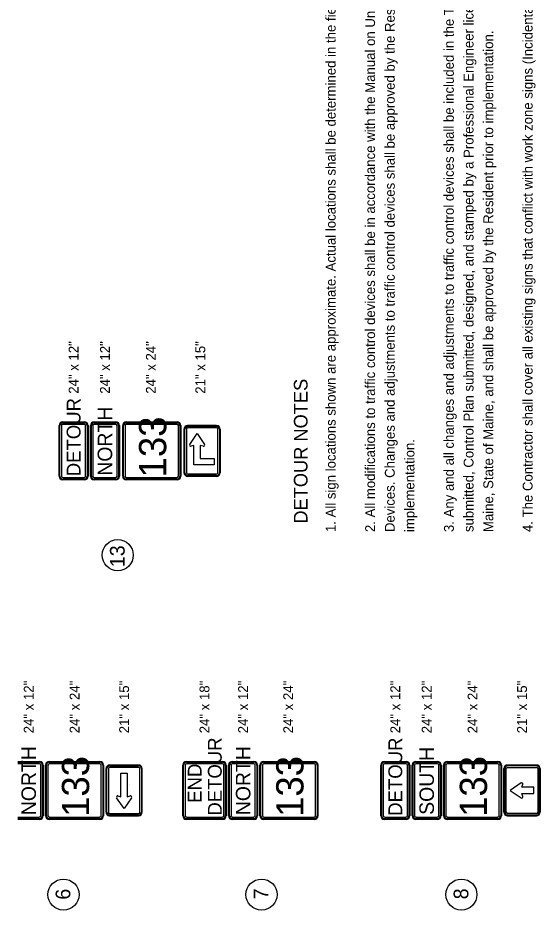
# Model space of a CAD drawing. Extents: x 1123038 to 1172987, y 554419 to 623636.
# Drawn here: x 1160788 to 1166729, y 559414 to 569560 of the extents above; entities that cross this region are included whole.
import ezdxf

# ---------------------------------------------------------------- set-up
doc = ezdxf.new("R2010")
doc.units = 0
for name, color, linetype in [('ANNOTATION', 7, 'Continuous'), ('D_Text_Standard', 7, 'Continuous'), ('Default', 7, 'Continuous'), ('SIGNS TRAFFIC', 7, 'Continuous')]:
    doc.layers.add(name, color=color, linetype=linetype)

msp = doc.modelspace()

# ---------------------------------------------------------------- linework, layer by layer
at = {"layer": 'D_Text_Standard'}
for centre in [(1161924, 563451), (1161307, 559591), (1163560, 559591), (1165833, 559591)]:
    msp.add_circle(centre, 177, dxfattribs=at)
at = {"layer": 'SIGNS TRAFFIC'}
for p, q in [((1163023, 564548), (1163023, 564476)), ((1161801, 560528), (1161801, 561023)), ((1166327, 561023), (1166327, 560528)), ((1161961, 560702), (1161961, 560971)), ((1161961, 560971), (1162033, 560971)), ((1162033, 560971), (1162033, 560702)), ((1166521, 560812), (1166532, 560845)), ((1166657, 560812), (1166521, 560812)), ((1166657, 560739), (1166657, 560812)), ((1161927, 560713), (1161961, 560702)), ((1162033, 560702), (1162066, 560713)), ((1166532, 560706), (1166521, 560739)), ((1166521, 560739), (1166657, 560739))]:
    msp.add_line(p, q, dxfattribs=at)
for points in [[(1161298, 564966), (1161546, 564966)], [(1161298, 564966), (1161546, 564966)], [(1161298, 564956), (1161546, 564956)], [(1161655, 564966), (1161902, 564966)], [(1161655, 564966), (1161902, 564966)], [(1161655, 564956), (1161902, 564956)], [(1162022, 564966), (1162600, 564966)], [(1162022, 564966), (1162600, 564966)], [(1162022, 564956), (1162600, 564956)], [(1161257, 564347), (1161257, 564925)], [(1161257, 564347), (1161257, 564925)], [(1161267, 564347), (1161267, 564925)], [(1161284, 564925), (1161284, 564347)], [(1161546, 564938), (1161298, 564938)], [(1161559, 564347), (1161559, 564925)], [(1161577, 564925), (1161577, 564347)], [(1161587, 564925), (1161587, 564347)], [(1161587, 564925), (1161587, 564347)], [(1161614, 564347), (1161614, 564925)], [(1161614, 564347), (1161614, 564925)], [(1161624, 564347), (1161624, 564925)], [(1161641, 564925), (1161641, 564347)], [(1161902, 564938), (1161655, 564938)], [(1161916, 564347), (1161916, 564925)], [(1161933, 564925), (1161933, 564347)], [(1161944, 564925), (1161944, 564347)], [(1161944, 564925), (1161944, 564347)], [(1161981, 564347), (1161981, 564925)], [(1161981, 564347), (1161981, 564925)], [(1161991, 564347), (1161991, 564925)], [(1162009, 564925), (1162009, 564347)], [(1162600, 564938), (1162022, 564938)], [(1162614, 564347), (1162614, 564925)], [(1162631, 564925), (1162631, 564347)], [(1162641, 564925), (1162641, 564347)], [(1162641, 564925), (1162641, 564347)], [(1162678, 564883), (1162678, 564388)], [(1162678, 564388), (1162678, 564883)], [(1162688, 564388), (1162688, 564883)], [(1162705, 564883), (1162705, 564388)], [(1163049, 564925), (1162719, 564925)], [(1162719, 564925), (1163049, 564925)], [(1162719, 564914), (1163049, 564914)], [(1163049, 564897), (1162719, 564897)], [(1163063, 564388), (1163063, 564883)], [(1163080, 564883), (1163080, 564388)], [(1163090, 564388), (1163090, 564883)], [(1163090, 564883), (1163090, 564388)], [(1162743, 564708), (1162827, 564832), (1162912, 564708)], [(1163023, 564476), (1162791, 564476), (1162791, 564699), (1162758, 564688)], [(1162897, 564688), (1162863, 564699), (1162863, 564548), (1163023, 564548)], [(1161298, 564333), (1161546, 564333)], [(1161655, 564333), (1161902, 564333)], [(1162022, 564333), (1162600, 564333)], [(1162719, 564375), (1163049, 564375)], [(1163049, 564358), (1162719, 564358)], [(1162719, 564347), (1163049, 564347)], [(1163049, 564347), (1162719, 564347)], [(1161546, 564316), (1161298, 564316)], [(1161546, 564306), (1161298, 564306)], [(1161546, 564306), (1161298, 564306)], [(1161902, 564316), (1161655, 564316)], [(1161902, 564306), (1161655, 564306)], [(1161902, 564306), (1161655, 564306)], [(1162600, 564316), (1162022, 564316)], [(1162600, 564306), (1162022, 564306)], [(1162600, 564306), (1162022, 564306)], [(1160788, 561106), (1161036, 561106)], [(1160788, 561106), (1161036, 561106)], [(1160788, 561095), (1161036, 561095)], [(1161145, 561106), (1161722, 561106)], [(1161145, 561106), (1161722, 561106)], [(1161145, 561095), (1161722, 561095)], [(1162705, 561106), (1163117, 561106)], [(1162705, 561106), (1163117, 561106)], [(1162705, 561095), (1163117, 561095)], [(1163226, 561106), (1163474, 561106)], [(1163226, 561106), (1163474, 561106)], [(1163226, 561095), (1163474, 561095)], [(1163583, 561106), (1164161, 561106)], [(1163583, 561106), (1164161, 561106)], [(1163583, 561095), (1164161, 561095)], [(1164957, 561106), (1165205, 561106)], [(1164957, 561106), (1165205, 561106)], [(1164957, 561095), (1165205, 561095)], [(1165314, 561106), (1165562, 561106)], [(1165314, 561106), (1165562, 561106)], [(1165314, 561095), (1165562, 561095)], [(1165671, 561106), (1166249, 561106)], [(1165671, 561106), (1166249, 561106)], [(1165671, 561095), (1166249, 561095)], [(1161036, 561078), (1160788, 561078)], [(1161049, 560487), (1161049, 561064)], [(1161066, 561064), (1161066, 560487)], [(1161077, 561064), (1161077, 560487)], [(1161077, 561064), (1161077, 560487)], [(1161104, 560487), (1161104, 561064)], [(1161104, 560487), (1161104, 561064)], [(1161114, 560487), (1161114, 561064)], [(1161131, 561064), (1161131, 560487)], [(1161722, 561078), (1161145, 561078)], [(1161736, 560487), (1161736, 561064)], [(1161753, 561064), (1161753, 560487)], [(1161764, 561064), (1161764, 560487)], [(1161764, 561064), (1161764, 560487)], [(1161790, 561023), (1161790, 560528)], [(1161818, 561023), (1161818, 560528)], [(1162162, 561064), (1161832, 561064)], [(1161832, 561054), (1162162, 561054)], [(1162162, 561037), (1161832, 561037)], [(1162175, 560528), (1162175, 561023)], [(1162193, 561023), (1162193, 560528)], [(1162203, 560528), (1162203, 561023)], [(1162663, 560487), (1162663, 561064)], [(1162663, 560487), (1162663, 561064)], [(1162674, 560487), (1162674, 561064)], [(1162691, 561064), (1162691, 560487)], [(1163117, 561078), (1162705, 561078)], [(1163131, 560487), (1163131, 561064)], [(1163148, 561064), (1163148, 560487)], [(1163158, 561064), (1163158, 560487)], [(1163158, 561064), (1163158, 560487)], [(1163185, 560487), (1163185, 561064)], [(1163185, 560487), (1163185, 561064)], [(1163195, 560487), (1163195, 561064)], [(1163213, 561064), (1163213, 560487)], [(1163474, 561078), (1163226, 561078)], [(1163488, 560487), (1163488, 561064)], [(1163505, 561064), (1163505, 560487)], [(1163515, 561064), (1163515, 560487)], [(1163515, 561064), (1163515, 560487)], [(1163542, 560487), (1163542, 561064)], [(1163542, 560487), (1163542, 561064)], [(1163552, 560487), (1163552, 561064)], [(1163569, 561064), (1163569, 560487)], [(1164161, 561078), (1163583, 561078)], [(1164174, 560487), (1164174, 561064)], [(1164192, 561064), (1164192, 560487)], [(1164202, 561064), (1164202, 560487)], [(1164202, 561064), (1164202, 560487)], [(1164916, 560487), (1164916, 561064)], [(1164916, 560487), (1164916, 561064)], [(1164927, 560487), (1164927, 561064)], [(1164944, 561064), (1164944, 560487)], [(1165205, 561078), (1164957, 561078)], [(1165219, 560487), (1165219, 561064)], [(1165236, 561064), (1165236, 560487)], [(1165246, 561064), (1165246, 560487)], [(1165246, 561064), (1165246, 560487)], [(1165273, 560487), (1165273, 561064)], [(1165273, 560487), (1165273, 561064)], [(1165283, 560487), (1165283, 561064)], [(1165301, 561064), (1165301, 560487)], [(1165562, 561078), (1165314, 561078)], [(1165576, 560487), (1165576, 561064)], [(1165593, 561064), (1165593, 560487)], [(1165603, 561064), (1165603, 560487)], [(1165603, 561064), (1165603, 560487)], [(1165630, 560487), (1165630, 561064)], [(1165630, 560487), (1165630, 561064)], [(1165640, 560487), (1165640, 561064)], [(1165657, 561064), (1165657, 560487)], [(1166249, 561078), (1165671, 561078)], [(1166262, 560487), (1166262, 561064)], [(1166280, 561064), (1166280, 560487)], [(1166290, 561064), (1166290, 560487)], [(1166290, 561064), (1166290, 560487)], [(1166317, 560528), (1166317, 561023)], [(1166317, 561023), (1166317, 560528)], [(1166344, 560528), (1166344, 561023)], [(1166358, 561064), (1166688, 561064)], [(1166688, 561064), (1166358, 561064)], [(1166688, 561054), (1166358, 561054)], [(1166358, 561037), (1166688, 561037)], [(1166702, 561023), (1166702, 560528)], [(1166719, 560528), (1166719, 561023)], [(1166729, 561023), (1166729, 560528)], [(1166729, 560528), (1166729, 561023)], [(1162054, 560846), (1162054, 560845)], [(1166513, 560860), (1166389, 560776), (1166513, 560691)], [(1162081, 560693), (1161997, 560569), (1161912, 560693)], [(1161832, 560514), (1162162, 560514)], [(1162162, 560497), (1161832, 560497)], [(1161832, 560487), (1162162, 560487)], [(1166688, 560514), (1166358, 560514)], [(1166358, 560497), (1166688, 560497)], [(1166688, 560487), (1166358, 560487)], [(1166358, 560487), (1166688, 560487)], [(1160788, 560473), (1161036, 560473)], [(1161036, 560456), (1160788, 560456)], [(1161036, 560446), (1160788, 560446)], [(1161036, 560446), (1160788, 560446)], [(1161145, 560473), (1161722, 560473)], [(1161722, 560456), (1161145, 560456)], [(1161722, 560446), (1161145, 560446)], [(1161722, 560446), (1161145, 560446)], [(1162705, 560473), (1163117, 560473)], [(1163117, 560456), (1162705, 560456)], [(1163117, 560446), (1162705, 560446)], [(1163117, 560446), (1162705, 560446)], [(1163226, 560473), (1163474, 560473)], [(1163474, 560456), (1163226, 560456)], [(1163474, 560446), (1163226, 560446)], [(1163474, 560446), (1163226, 560446)], [(1163583, 560473), (1164161, 560473)], [(1164161, 560456), (1163583, 560456)], [(1164161, 560446), (1163583, 560446)], [(1164161, 560446), (1163583, 560446)], [(1164957, 560473), (1165205, 560473)], [(1165205, 560456), (1164957, 560456)], [(1165205, 560446), (1164957, 560446)], [(1165205, 560446), (1164957, 560446)], [(1165314, 560473), (1165562, 560473)], [(1165562, 560456), (1165314, 560456)], [(1165562, 560446), (1165314, 560446)], [(1165562, 560446), (1165314, 560446)], [(1165671, 560473), (1166249, 560473)], [(1166249, 560456), (1165671, 560456)], [(1166249, 560446), (1165671, 560446)], [(1166249, 560446), (1165671, 560446)]]:
    msp.add_lwpolyline(points, dxfattribs=at)
for centre, radius, start, end in [((1161298, 564925), 41.2, 90, 180), ((1161298, 564925), 41.2, 90, 180), ((1161298, 564925), 30.9, 90, 180), ((1161546, 564925), 41.2, 360, 90), ((1161546, 564925), 41.2, 360, 90), ((1161546, 564925), 30.9, 360, 90), ((1161655, 564925), 41.2, 90, 180), ((1161655, 564925), 41.2, 90, 180), ((1161655, 564925), 30.9, 90, 180), ((1161902, 564925), 41.2, 360, 90), ((1161902, 564925), 41.2, 360, 90), ((1161902, 564925), 30.9, 360, 90), ((1162022, 564925), 41.2, 90, 180), ((1162022, 564925), 41.2, 90, 180), ((1162022, 564925), 30.9, 90, 180), ((1162600, 564925), 41.2, 360, 90), ((1162600, 564925), 41.2, 360, 90), ((1162600, 564925), 30.9, 360, 90), ((1161298, 564925), 13.7, 90, 180), ((1161546, 564925), 13.7, 360, 90), ((1161655, 564925), 13.7, 90, 180), ((1161902, 564925), 13.7, 360, 90), ((1162022, 564925), 13.7, 90, 180), ((1162600, 564925), 13.7, 360, 90), ((1162719, 564883), 41.2, 90, 180), ((1162719, 564883), 41.2, 90, 180), ((1162719, 564883), 30.9, 90, 180), ((1162719, 564883), 13.7, 90, 180), ((1163049, 564883), 41.2, 360, 90), ((1163049, 564883), 41.2, 360, 90), ((1163049, 564883), 30.9, 360, 90), ((1163049, 564883), 13.7, 360, 90), ((1162754, 564701), 12.9, 145.6763, 287.8128), ((1162901, 564701), 12.9, 252.1872, 34.3237), ((1161298, 564347), 41.2, 180, 270), ((1161298, 564347), 41.2, 180, 270), ((1161298, 564347), 30.9, 180, 270), ((1161298, 564347), 13.7, 180, 270), ((1161546, 564347), 41.2, 270, 360), ((1161546, 564347), 41.2, 270, 360), ((1161546, 564347), 30.9, 270, 360), ((1161546, 564347), 13.7, 270, 360), ((1161655, 564347), 41.2, 180, 270), ((1161655, 564347), 41.2, 180, 270), ((1161655, 564347), 30.9, 180, 270), ((1161655, 564347), 13.7, 180, 270), ((1161902, 564347), 41.2, 270, 360), ((1161902, 564347), 41.2, 270, 360), ((1161902, 564347), 30.9, 270, 360), ((1161902, 564347), 13.7, 270, 360), ((1162022, 564347), 41.2, 180, 270), ((1162022, 564347), 41.2, 180, 270), ((1162022, 564347), 30.9, 180, 270), ((1162022, 564347), 13.7, 180, 270), ((1162600, 564347), 41.2, 270, 360), ((1162600, 564347), 41.2, 270, 360), ((1162600, 564347), 30.9, 270, 360), ((1162600, 564347), 13.7, 270, 360), ((1162719, 564388), 41.2, 180, 270), ((1162719, 564388), 41.2, 180, 270), ((1162719, 564388), 30.9, 180, 270), ((1162719, 564388), 13.7, 180, 270), ((1163049, 564388), 41.2, 270, 0), ((1163049, 564388), 41.2, 270, 0), ((1163049, 564388), 30.9, 270, 0), ((1163049, 564388), 13.7, 270, 0), ((1161036, 561064), 41.2, 360, 90), ((1161036, 561064), 41.2, 360, 90), ((1161036, 561064), 30.9, 360, 90), ((1161145, 561064), 41.2, 90, 180), ((1161145, 561064), 41.2, 90, 180), ((1161145, 561064), 30.9, 90, 180), ((1161722, 561064), 41.2, 360, 90), ((1161722, 561064), 41.2, 360, 90), ((1161722, 561064), 30.9, 360, 90), ((1162705, 561064), 41.2, 90, 180), ((1162705, 561064), 41.2, 90, 180), ((1162705, 561064), 30.9, 90, 180), ((1163117, 561064), 41.2, 360, 90), ((1163117, 561064), 41.2, 360, 90), ((1163117, 561064), 30.9, 360, 90), ((1163226, 561064), 41.2, 90, 180), ((1163226, 561064), 41.2, 90, 180), ((1163226, 561064), 30.9, 90, 180), ((1163474, 561064), 41.2, 360, 90), ((1163474, 561064), 41.2, 360, 90), ((1163474, 561064), 30.9, 360, 90), ((1163583, 561064), 41.2, 90, 180), ((1163583, 561064), 41.2, 90, 180), ((1163583, 561064), 30.9, 90, 180), ((1164161, 561064), 41.2, 360, 90), ((1164161, 561064), 41.2, 360, 90), ((1164161, 561064), 30.9, 360, 90), ((1164957, 561064), 41.2, 90, 180), ((1164957, 561064), 41.2, 90, 180), ((1164957, 561064), 30.9, 90, 180), ((1165205, 561064), 41.2, 360, 90), ((1165205, 561064), 41.2, 360, 90), ((1165205, 561064), 30.9, 360, 90), ((1165314, 561064), 41.2, 90, 180), ((1165314, 561064), 41.2, 90, 180), ((1165314, 561064), 30.9, 90, 180), ((1165562, 561064), 41.2, 360, 90), ((1165562, 561064), 41.2, 360, 90), ((1165562, 561064), 30.9, 360, 90), ((1165671, 561064), 41.2, 90, 180), ((1165671, 561064), 41.2, 90, 180), ((1165671, 561064), 30.9, 90, 180), ((1166249, 561064), 41.2, 360, 90), ((1166249, 561064), 41.2, 360, 90), ((1166249, 561064), 30.9, 360, 90), ((1161036, 561064), 13.7, 360, 90), ((1161145, 561064), 13.7, 90, 180), ((1161722, 561064), 13.7, 360, 90), ((1161832, 561023), 41.2, 90, 180), ((1161832, 561023), 30.9, 90, 180), ((1161832, 561023), 13.7, 90, 180), ((1162162, 561023), 41.2, 360, 90), ((1162162, 561023), 30.9, 360, 90), ((1162162, 561023), 13.7, 360, 90), ((1162705, 561064), 13.7, 90, 180), ((1163117, 561064), 13.7, 360, 90), ((1163226, 561064), 13.7, 90, 180), ((1163474, 561064), 13.7, 360, 90), ((1163583, 561064), 13.7, 90, 180), ((1164161, 561064), 13.7, 360, 90), ((1164957, 561064), 13.7, 90, 180), ((1165205, 561064), 13.7, 360, 90), ((1165314, 561064), 13.7, 90, 180), ((1165562, 561064), 13.7, 360, 90), ((1165671, 561064), 13.7, 90, 180), ((1166249, 561064), 13.7, 360, 90), ((1166358, 561023), 41.2, 90, 180), ((1166358, 561023), 41.2, 90, 180), ((1166358, 561023), 30.9, 90, 180), ((1166358, 561023), 13.7, 90, 180), ((1166688, 561023), 41.2, 360, 90), ((1166688, 561023), 41.2, 360, 90), ((1166688, 561023), 30.9, 360, 90), ((1166688, 561023), 13.7, 360, 90), ((1166520, 560849), 12.9, 342.1872, 124.3237), ((1161923, 560700), 12.9, 72.1872, 214.3237), ((1162070, 560700), 12.9, 325.6763, 107.8128), ((1166520, 560702), 12.9, 235.6763, 17.8128), ((1161036, 560487), 41.2, 270, 360), ((1161036, 560487), 41.2, 270, 360), ((1161036, 560487), 30.9, 270, 360), ((1161036, 560487), 13.7, 270, 360), ((1161145, 560487), 41.2, 180, 270), ((1161145, 560487), 41.2, 180, 270), ((1161145, 560487), 30.9, 180, 270), ((1161145, 560487), 13.7, 180, 270), ((1161722, 560487), 41.2, 270, 360), ((1161722, 560487), 41.2, 270, 360), ((1161722, 560487), 30.9, 270, 360), ((1161722, 560487), 13.7, 270, 360), ((1161832, 560528), 41.2, 180, 270), ((1161832, 560528), 30.9, 180, 270), ((1161832, 560528), 13.7, 180, 270), ((1162162, 560528), 41.2, 270, 0), ((1162162, 560528), 30.9, 270, 0), ((1162162, 560528), 13.7, 270, 0), ((1162705, 560487), 41.2, 180, 270), ((1162705, 560487), 41.2, 180, 270), ((1162705, 560487), 30.9, 180, 270), ((1162705, 560487), 13.7, 180, 270), ((1163117, 560487), 41.2, 270, 360), ((1163117, 560487), 41.2, 270, 360), ((1163117, 560487), 30.9, 270, 360), ((1163117, 560487), 13.7, 270, 360), ((1163226, 560487), 41.2, 180, 270), ((1163226, 560487), 41.2, 180, 270), ((1163226, 560487), 30.9, 180, 270), ((1163226, 560487), 13.7, 180, 270), ((1163474, 560487), 41.2, 270, 360), ((1163474, 560487), 41.2, 270, 360), ((1163474, 560487), 30.9, 270, 360), ((1163474, 560487), 13.7, 270, 360), ((1163583, 560487), 41.2, 180, 270), ((1163583, 560487), 41.2, 180, 270), ((1163583, 560487), 30.9, 180, 270), ((1163583, 560487), 13.7, 180, 270), ((1164161, 560487), 41.2, 270, 360), ((1164161, 560487), 41.2, 270, 360), ((1164161, 560487), 30.9, 270, 360), ((1164161, 560487), 13.7, 270, 360), ((1164957, 560487), 41.2, 180, 270), ((1164957, 560487), 41.2, 180, 270), ((1164957, 560487), 30.9, 180, 270), ((1164957, 560487), 13.7, 180, 270), ((1165205, 560487), 41.2, 270, 360), ((1165205, 560487), 41.2, 270, 360), ((1165205, 560487), 30.9, 270, 360), ((1165205, 560487), 13.7, 270, 360), ((1165314, 560487), 41.2, 180, 270), ((1165314, 560487), 41.2, 180, 270), ((1165314, 560487), 30.9, 180, 270), ((1165314, 560487), 13.7, 180, 270), ((1165562, 560487), 41.2, 270, 360), ((1165562, 560487), 41.2, 270, 360), ((1165562, 560487), 30.9, 270, 360), ((1165562, 560487), 13.7, 270, 360), ((1165671, 560487), 41.2, 180, 270), ((1165671, 560487), 41.2, 180, 270), ((1165671, 560487), 30.9, 180, 270), ((1165671, 560487), 13.7, 180, 270), ((1166249, 560487), 41.2, 270, 360), ((1166249, 560487), 41.2, 270, 360), ((1166249, 560487), 30.9, 270, 360), ((1166249, 560487), 13.7, 270, 360), ((1166358, 560528), 41.2, 180, 270), ((1166358, 560528), 41.2, 180, 270), ((1166358, 560528), 30.9, 180, 270), ((1166358, 560528), 13.7, 180, 270), ((1166688, 560528), 41.2, 270, 0), ((1166688, 560528), 41.2, 270, 0), ((1166688, 560528), 30.9, 270, 0), ((1166688, 560528), 13.7, 270, 0)]:
    msp.add_arc(centre, radius, start, end, dxfattribs=at)

# ---------------------------------------------------------------- texts
at = {"layer": 'ANNOTATION'}
msp.add_text('DETOUR NOTES', height=155, rotation=90, dxfattribs=at).set_placement((1164083, 563809))
at = {"layer": 'D_Text_Standard'}
for s, height, p in [('24" x 12"', 112, (1161478, 565286)), ('24" x 12"', 112, (1161835, 565286)), ('24" x 24"', 112, (1162357, 565286)), ('21" x 15"', 112, (1162920, 565286)), ('13', 167.1, (1162003, 563314)), ('24" x 12"', 112, (1160968, 561425)), ('24" x 24"', 112, (1161490, 561425)), ('21" x 15"', 112, (1162053, 561425)), ('24" x 18"', 112, (1162967, 561425)), ('24" x 12"', 112, (1163406, 561425)), ('24" x 24"', 112, (1163919, 561425)), ('24" x 12"', 112, (1165137, 561425)), ('24" x 12"', 112, (1165494, 561425)), ('24" x 24"', 112, (1166016, 561425)), ('21" x 15"', 112, (1166579, 561425)), ('6', 167, (1161385, 559533)), ('7', 167, (1163638, 559537)), ('8', 167, (1165912, 559537))]:
    msp.add_text(s, height=height, rotation=90, dxfattribs=at).set_placement(p)
at = {"layer": 'Default'}
for s, p in [('2. All modifications to traffic control devices shall be in accordance with the Manual on Uniform Traffic Control ', (1164851, 563713)), ('submitted, Control Plan submitted, designed, and stamped by a Professional Engineer licensed in the State of ', (1165971, 563713)), ('1. All sign locations shown are approximate. Actual locations shall be determined in the field by the Resident.', (1164403, 563713)), ('3. Any and all changes and adjustments to traffic control devices shall be included in the Traffic Control Plan ', (1165747, 563713)), ('4. The Contractor shall cover all existing signs that conflict with work zone signs (Incidental to item 652.35)', (1166643, 563713)), ('Devices. Changes and adjustments to traffic control devices shall be approved by the Resident prior to ', (1165075, 563713)), ('Maine, State of Maine, and shall be approved by the Resident prior to implementation.', (1166195, 563713)), ('implementation.', (1165299, 563713))]:
    msp.add_text(s, height=112, rotation=90, dxfattribs=at).set_placement(p)
at = {"layer": 'SIGNS TRAFFIC'}
for s, height, p in [('DETOUR', 157.5, (1161501, 564348)), ('NORTH', 165, (1161861, 564354)), ('133', 310, (1162476, 564335)), ('DETOUR', 157.5, (1163107, 560489)), ('DETOUR', 157.5, (1165160, 560487)), ('NORTH', 165, (1160994, 560494)), ('NORTH', 165, (1163433, 560494)), ('SOUTH', 165, (1165521, 560498)), ('133', 310, (1161599, 560475)), ('133', 310, (1164037, 560475)), ('133', 310, (1166125, 560475)), ('END', 157.5, (1162878, 560635))]:
    msp.add_text(s, height=height, rotation=90, dxfattribs=at).set_placement(p)

doc.saveas('drawing.dxf')
